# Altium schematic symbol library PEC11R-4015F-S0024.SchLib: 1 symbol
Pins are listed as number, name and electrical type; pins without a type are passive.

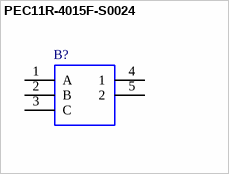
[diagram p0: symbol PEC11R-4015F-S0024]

## PEC11R-4015F-S0024
designator B?
Bourns 24 Pulse Incremental Mechanical Rotary Encoder with a 6 mm Flat Shaft (Not Indexed), Through Hole
footprint PEC12R-4XXXF-SXXXX_1
pins: 1 A, 2 B, 3 C, 4 1, 5 2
